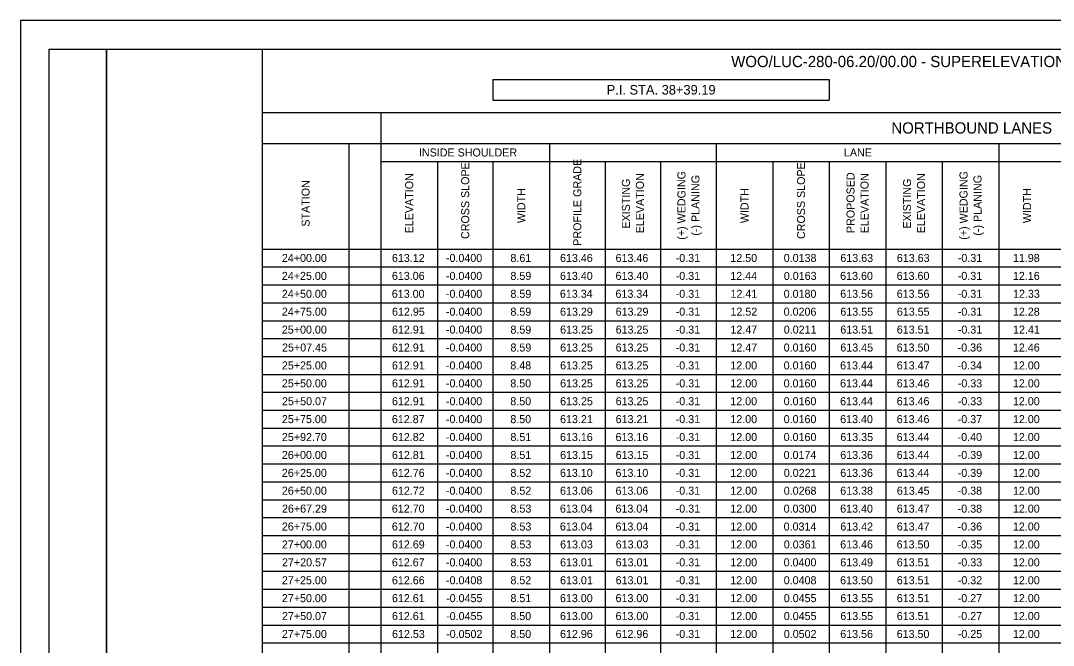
# Model space of a CAD drawing. Extents: x 0 to 34, y 0 to 22.
# Drawn here: x 0 to 18.06, y 11.08 to 22 of the extents above; entities that cross this region are included whole.
import ezdxf

# ---------------------------------------------------------------- set-up
doc = ezdxf.new("R2010")
doc.units = 0
for name, color, linetype in [('SH_Border', 7, 'Continuous'), ('SH_Cut_Line', 7, 'Continuous'), ('SH_Text', 7, 'Continuous')]:
    doc.layers.add(name, color=color, linetype=linetype)

msp = doc.modelspace()

# ---------------------------------------------------------------- linework, layer by layer
at = {"layer": 'SH_Border'}
for points in [[(0.5, 21.5), (1.5, 21.5), (1.5, 0.5), (0.5, 0.5)], [(1.5, 21.5), (33.5, 21.5), (33.5, 0.5), (1.5, 0.5)]]:
    msp.add_lwpolyline(points, close=True, dxfattribs=at)
at = {"layer": 'SH_Cut_Line'}
msp.add_lwpolyline([(0, 0), (34, 0), (34, 22), (0, 22)], close=True, dxfattribs=at)
at = {"layer": 'SH_Text'}
for p, q in [((4.225, 21.5), (5.74, 21.5)), ((4.225, 21.5), (4.225, 0.484)), ((8.26, 20.973), (14.14, 20.973)), ((8.26, 20.973), (8.26, 20.611)), ((14.14, 20.973), (14.14, 20.611)), ((8.26, 20.611), (14.14, 20.611)), ((4.225, 20.396), (29.277, 20.396)), ((6.3, 20.396), (6.3, 0.484)), ((4.225, 19.853), (29.277, 19.853)), ((5.74, 19.853), (5.74, 0.484)), ((9.249, 19.853), (9.249, 0.484)), ((12.164, 19.853), (12.164, 0.484)), ((17.105, 19.853), (17.105, 0.484)), ((6.3, 19.54), (26.938, 19.54)), ((7.289, 19.54), (7.289, 0.484)), ((8.26, 19.54), (8.26, 0.484)), ((10.22, 19.54), (10.22, 0.484)), ((11.192, 19.54), (11.192, 0.484)), ((13.152, 19.54), (13.152, 0.484)), ((14.14, 19.54), (14.14, 0.484)), ((15.129, 19.54), (15.129, 0.484)), ((16.117, 19.54), (16.117, 0.484)), ((4.225, 18.008), (29.277, 18.008)), ((4.225, 17.695), (29.277, 17.695)), ((4.225, 17.382), (29.277, 17.382)), ((4.225, 17.069), (29.277, 17.069)), ((4.225, 16.756), (29.277, 16.756)), ((4.225, 16.444), (29.277, 16.444)), ((4.225, 16.131), (29.277, 16.131)), ((4.225, 15.818), (29.277, 15.818)), ((4.225, 15.505), (29.277, 15.505)), ((4.225, 15.192), (29.277, 15.192)), ((4.225, 14.879), (29.277, 14.879)), ((4.225, 14.566), (29.277, 14.566)), ((4.225, 14.253), (29.277, 14.253)), ((4.225, 13.94), (29.277, 13.94)), ((4.225, 13.627), (29.277, 13.627)), ((4.225, 13.314), (29.277, 13.314)), ((4.225, 13.001), (29.277, 13.001)), ((4.225, 12.688), (29.277, 12.688)), ((4.225, 12.375), (29.277, 12.375)), ((4.225, 12.062), (29.277, 12.062)), ((4.225, 11.749), (29.277, 11.749)), ((4.225, 11.436), (29.277, 11.436)), ((4.225, 11.124), (29.277, 11.124))]:
    msp.add_line(p, q, dxfattribs=at)

# ---------------------------------------------------------------- texts
for s, height, p in [('WOO/LUC-280-06.20/00.00 - SUPERELEVATION TABLE', 0.196, (12.425, 21.188)), ('P.I. STA. 38+39.19', 0.168, (10.248, 20.708)), ('NORTHBOUND LANES', 0.196, (15.226, 20.027)), ('INSIDE SHOULDER', 0.14, (6.965, 19.626)), ('LANE', 0.14, (14.397, 19.626)), ('24+00.00', 0.14, (4.568, 17.782)), ('613.12', 0.14, (6.493, 17.782)), ('-0.0400', 0.14, (7.437, 17.782)), ('8.61', 0.14, (8.565, 17.782)), ('613.46', 0.14, (9.432, 17.782)), ('613.46', 0.14, (10.403, 17.782)), ('-0.31', 0.14, (11.455, 17.782)), ('12.50', 0.14, (12.41, 17.782)), ('0.0138', 0.14, (13.344, 17.782)), ('613.63', 0.14, (14.334, 17.782)), ('613.63', 0.14, (15.322, 17.782)), ('-0.31', 0.14, (16.388, 17.782)), ('11.98', 0.14, (17.352, 17.782)), ('24+25.00', 0.14, (4.568, 17.469)), ('613.06', 0.14, (6.492, 17.469)), ('-0.0400', 0.14, (7.437, 17.469)), ('8.59', 0.14, (8.565, 17.469)), ('613.40', 0.14, (9.431, 17.469)), ('613.40', 0.14, (10.403, 17.469)), ('-0.31', 0.14, (11.455, 17.469)), ('12.44', 0.14, (12.41, 17.469)), ('0.0163', 0.14, (13.346, 17.469)), ('613.60', 0.14, (14.331, 17.469)), ('613.60', 0.14, (15.319, 17.469)), ('-0.31', 0.14, (16.388, 17.469)), ('12.16', 0.14, (17.352, 17.469)), ('24+50.00', 0.14, (4.568, 17.156)), ('613.00', 0.14, (6.491, 17.156)), ('-0.0400', 0.14, (7.437, 17.156)), ('8.59', 0.14, (8.565, 17.156)), ('613.34', 0.14, (9.43, 17.156)), ('613.34', 0.14, (10.402, 17.156)), ('-0.31', 0.14, (11.455, 17.156)), ('12.41', 0.14, (12.413, 17.156)), ('0.0180', 0.14, (13.343, 17.156)), ('613.56', 0.14, (14.332, 17.156)), ('613.56', 0.14, (15.32, 17.156)), ('-0.31', 0.14, (16.388, 17.156)), ('12.33', 0.14, (17.354, 17.156)), ('24+75.00', 0.14, (4.568, 16.843)), ('612.95', 0.14, (6.494, 16.843)), ('-0.0400', 0.14, (7.437, 16.843)), ('8.59', 0.14, (8.565, 16.843)), ('613.29', 0.14, (9.433, 16.843)), ('613.29', 0.14, (10.405, 16.843)), ('-0.31', 0.14, (11.455, 16.843)), ('12.52', 0.14, (12.413, 16.843)), ('0.0206', 0.14, (13.343, 16.843)), ('613.55', 0.14, (14.334, 16.843)), ('613.55', 0.14, (15.322, 16.843)), ('-0.31', 0.14, (16.388, 16.843)), ('12.28', 0.14, (17.352, 16.843)), ('25+00.00', 0.14, (4.568, 16.53)), ('612.91', 0.14, (6.493, 16.53)), ('-0.0400', 0.14, (7.437, 16.53)), ('8.59', 0.14, (8.565, 16.53)), ('613.25', 0.14, (9.434, 16.53)), ('613.25', 0.14, (10.405, 16.53)), ('-0.31', 0.14, (11.455, 16.53)), ('12.47', 0.14, (12.412, 16.53)), ('0.0211', 0.14, (13.345, 16.53)), ('613.51', 0.14, (14.333, 16.53)), ('613.51', 0.14, (15.321, 16.53)), ('-0.31', 0.14, (16.388, 16.53)), ('12.41', 0.14, (17.354, 16.53)), ('25+07.45', 0.14, (4.571, 16.217)), ('612.91', 0.14, (6.493, 16.217)), ('-0.0400', 0.14, (7.437, 16.217)), ('8.59', 0.14, (8.565, 16.217)), ('613.25', 0.14, (9.434, 16.217)), ('613.25', 0.14, (10.405, 16.217)), ('-0.31', 0.14, (11.455, 16.217)), ('12.47', 0.14, (12.412, 16.217)), ('0.0160', 0.14, (13.343, 16.217)), ('613.45', 0.14, (14.334, 16.217)), ('613.50', 0.14, (15.319, 16.217)), ('-0.36', 0.14, (16.386, 16.217)), ('12.46', 0.14, (17.352, 16.217)), ('25+25.00', 0.14, (4.568, 15.904)), ('612.91', 0.14, (6.493, 15.904)), ('-0.0400', 0.14, (7.437, 15.904)), ('8.48', 0.14, (8.563, 15.904)), ('613.25', 0.14, (9.434, 15.904)), ('613.25', 0.14, (10.405, 15.904)), ('-0.31', 0.14, (11.455, 15.904)), ('12.00', 0.14, (12.41, 15.904)), ('0.0160', 0.14, (13.343, 15.904)), ('613.44', 0.14, (14.33, 15.904)), ('613.47', 0.14, (15.321, 15.904)), ('-0.34', 0.14, (16.385, 15.904)), ('12.00', 0.14, (17.352, 15.904)), ('25+50.00', 0.14, (4.568, 15.591)), ('612.91', 0.14, (6.493, 15.591)), ('-0.0400', 0.14, (7.437, 15.591)), ('8.50', 0.14, (8.563, 15.591)), ('613.25', 0.14, (9.434, 15.591)), ('613.25', 0.14, (10.405, 15.591)), ('-0.31', 0.14, (11.455, 15.591)), ('12.00', 0.14, (12.41, 15.591)), ('0.0160', 0.14, (13.343, 15.591)), ('613.44', 0.14, (14.33, 15.591)), ('613.46', 0.14, (15.32, 15.591)), ('-0.33', 0.14, (16.388, 15.591)), ('12.00', 0.14, (17.352, 15.591)), ('25+50.07', 0.14, (4.57, 15.278)), ('612.91', 0.14, (6.493, 15.278)), ('-0.0400', 0.14, (7.437, 15.278)), ('8.50', 0.14, (8.563, 15.278)), ('613.25', 0.14, (9.434, 15.278)), ('613.25', 0.14, (10.405, 15.278)), ('-0.31', 0.14, (11.455, 15.278)), ('12.00', 0.14, (12.41, 15.278)), ('0.0160', 0.14, (13.343, 15.278)), ('613.44', 0.14, (14.33, 15.278)), ('613.46', 0.14, (15.32, 15.278)), ('-0.33', 0.14, (16.388, 15.278)), ('12.00', 0.14, (17.352, 15.278)), ('25+75.00', 0.14, (4.568, 14.965)), ('612.87', 0.14, (6.492, 14.965)), ('-0.0400', 0.14, (7.437, 14.965)), ('8.50', 0.14, (8.563, 14.965)), ('613.21', 0.14, (9.433, 14.965)), ('613.21', 0.14, (10.405, 14.965)), ('-0.31', 0.14, (11.455, 14.965)), ('12.00', 0.14, (12.41, 14.965)), ('0.0160', 0.14, (13.343, 14.965)), ('613.40', 0.14, (14.331, 14.965)), ('613.46', 0.14, (15.32, 14.965)), ('-0.37', 0.14, (16.387, 14.965)), ('12.00', 0.14, (17.352, 14.965)), ('25+92.70', 0.14, (4.568, 14.652)), ('612.82', 0.14, (6.493, 14.652)), ('-0.0400', 0.14, (7.437, 14.652)), ('8.51', 0.14, (8.565, 14.652)), ('613.16', 0.14, (9.432, 14.652)), ('613.16', 0.14, (10.403, 14.652)), ('-0.31', 0.14, (11.455, 14.652)), ('12.00', 0.14, (12.41, 14.652)), ('0.0160', 0.14, (13.343, 14.652)), ('613.35', 0.14, (14.334, 14.652)), ('613.44', 0.14, (15.319, 14.652)), ('-0.40', 0.14, (16.385, 14.652)), ('12.00', 0.14, (17.352, 14.652)), ('26+00.00', 0.14, (4.568, 14.339)), ('612.81', 0.14, (6.493, 14.339)), ('-0.0400', 0.14, (7.437, 14.339)), ('8.51', 0.14, (8.565, 14.339)), ('613.15', 0.14, (9.434, 14.339)), ('613.15', 0.14, (10.405, 14.339)), ('-0.31', 0.14, (11.455, 14.339)), ('12.00', 0.14, (12.41, 14.339)), ('0.0174', 0.14, (13.342, 14.339)), ('613.36', 0.14, (14.332, 14.339)), ('613.44', 0.14, (15.319, 14.339)), ('-0.39', 0.14, (16.387, 14.339)), ('12.00', 0.14, (17.352, 14.339)), ('26+25.00', 0.14, (4.568, 14.026)), ('612.76', 0.14, (6.492, 14.026)), ('-0.0400', 0.14, (7.437, 14.026)), ('8.52', 0.14, (8.565, 14.026)), ('613.10', 0.14, (9.431, 14.026)), ('613.10', 0.14, (10.403, 14.026)), ('-0.31', 0.14, (11.455, 14.026)), ('12.00', 0.14, (12.41, 14.026)), ('0.0221', 0.14, (13.345, 14.026)), ('613.36', 0.14, (14.332, 14.026)), ('613.44', 0.14, (15.319, 14.026)), ('-0.39', 0.14, (16.387, 14.026)), ('12.00', 0.14, (17.352, 14.026)), ('26+50.00', 0.14, (4.568, 13.714)), ('612.72', 0.14, (6.493, 13.714)), ('-0.0400', 0.14, (7.437, 13.714)), ('8.52', 0.14, (8.565, 13.714)), ('613.06', 0.14, (9.432, 13.714)), ('613.06', 0.14, (10.403, 13.714)), ('-0.31', 0.14, (11.455, 13.714)), ('12.00', 0.14, (12.41, 13.714)), ('0.0268', 0.14, (13.344, 13.714)), ('613.38', 0.14, (14.332, 13.714)), ('613.45', 0.14, (15.322, 13.714)), ('-0.38', 0.14, (16.386, 13.714)), ('12.00', 0.14, (17.352, 13.714)), ('26+67.29', 0.14, (4.57, 13.401)), ('612.70', 0.14, (6.491, 13.401)), ('-0.0400', 0.14, (7.437, 13.401)), ('8.53', 0.14, (8.566, 13.401)), ('613.04', 0.14, (9.43, 13.401)), ('613.04', 0.14, (10.402, 13.401)), ('-0.31', 0.14, (11.455, 13.401)), ('12.00', 0.14, (12.41, 13.401)), ('0.0300', 0.14, (13.343, 13.401)), ('613.40', 0.14, (14.331, 13.401)), ('613.47', 0.14, (15.321, 13.401)), ('-0.38', 0.14, (16.386, 13.401)), ('12.00', 0.14, (17.352, 13.401)), ('26+75.00', 0.14, (4.568, 13.088)), ('612.70', 0.14, (6.491, 13.088)), ('-0.0400', 0.14, (7.437, 13.088)), ('8.53', 0.14, (8.566, 13.088)), ('613.04', 0.14, (9.43, 13.088)), ('613.04', 0.14, (10.402, 13.088)), ('-0.31', 0.14, (11.455, 13.088)), ('12.00', 0.14, (12.41, 13.088)), ('0.0314', 0.14, (13.342, 13.088)), ('613.42', 0.14, (14.333, 13.088)), ('613.47', 0.14, (15.321, 13.088)), ('-0.36', 0.14, (16.386, 13.088)), ('12.00', 0.14, (17.352, 13.088)), ('27+00.00', 0.14, (4.568, 12.775)), ('612.69', 0.14, (6.493, 12.775)), ('-0.0400', 0.14, (7.437, 12.775)), ('8.53', 0.14, (8.566, 12.775)), ('613.03', 0.14, (9.434, 12.775)), ('613.03', 0.14, (10.406, 12.775)), ('-0.31', 0.14, (11.455, 12.775)), ('12.00', 0.14, (12.41, 12.775)), ('0.0361', 0.14, (13.345, 12.775)), ('613.46', 0.14, (14.332, 12.775)), ('613.50', 0.14, (15.319, 12.775)), ('-0.35', 0.14, (16.388, 12.775)), ('12.00', 0.14, (17.352, 12.775)), ('27+20.57', 0.14, (4.57, 12.462)), ('612.67', 0.14, (6.492, 12.462)), ('-0.0400', 0.14, (7.437, 12.462)), ('8.53', 0.14, (8.566, 12.462)), ('613.01', 0.14, (9.433, 12.462)), ('613.01', 0.14, (10.405, 12.462)), ('-0.31', 0.14, (11.455, 12.462)), ('12.00', 0.14, (12.41, 12.462)), ('0.0400', 0.14, (13.343, 12.462)), ('613.49', 0.14, (14.333, 12.462)), ('613.51', 0.14, (15.321, 12.462)), ('-0.33', 0.14, (16.388, 12.462)), ('12.00', 0.14, (17.352, 12.462)), ('27+25.00', 0.14, (4.568, 12.149)), ('612.66', 0.14, (6.492, 12.149)), ('-0.0408', 0.14, (7.438, 12.149)), ('8.52', 0.14, (8.565, 12.149)), ('613.01', 0.14, (9.433, 12.149)), ('613.01', 0.14, (10.405, 12.149)), ('-0.31', 0.14, (11.455, 12.149)), ('12.00', 0.14, (12.41, 12.149)), ('0.0408', 0.14, (13.344, 12.149)), ('613.50', 0.14, (14.331, 12.149)), ('613.51', 0.14, (15.321, 12.149)), ('-0.32', 0.14, (16.388, 12.149)), ('12.00', 0.14, (17.352, 12.149)), ('27+50.00', 0.14, (4.568, 11.836)), ('612.61', 0.14, (6.493, 11.836)), ('-0.0455', 0.14, (7.44, 11.836)), ('8.51', 0.14, (8.565, 11.836)), ('613.00', 0.14, (9.431, 11.836)), ('613.00', 0.14, (10.403, 11.836)), ('-0.31', 0.14, (11.455, 11.836)), ('12.00', 0.14, (12.41, 11.836)), ('0.0455', 0.14, (13.345, 11.836)), ('613.55', 0.14, (14.334, 11.836)), ('613.51', 0.14, (15.321, 11.836)), ('-0.27', 0.14, (16.387, 11.836)), ('12.00', 0.14, (17.352, 11.836)), ('27+50.07', 0.14, (4.57, 11.523)), ('612.61', 0.14, (6.493, 11.523)), ('-0.0455', 0.14, (7.44, 11.523)), ('8.50', 0.14, (8.563, 11.523)), ('613.00', 0.14, (9.431, 11.523)), ('613.00', 0.14, (10.403, 11.523)), ('-0.31', 0.14, (11.455, 11.523)), ('12.00', 0.14, (12.41, 11.523)), ('0.0455', 0.14, (13.345, 11.523)), ('613.55', 0.14, (14.334, 11.523)), ('613.51', 0.14, (15.321, 11.523)), ('-0.27', 0.14, (16.387, 11.523)), ('12.00', 0.14, (17.352, 11.523)), ('27+75.00', 0.14, (4.568, 11.21)), ('612.53', 0.14, (6.494, 11.21)), ('-0.0502', 0.14, (7.44, 11.21)), ('8.50', 0.14, (8.563, 11.21)), ('612.96', 0.14, (9.432, 11.21)), ('612.96', 0.14, (10.403, 11.21)), ('-0.31', 0.14, (11.455, 11.21)), ('12.00', 0.14, (12.41, 11.21)), ('0.0502', 0.14, (13.345, 11.21)), ('613.56', 0.14, (14.332, 11.21)), ('613.50', 0.14, (15.319, 11.21)), ('-0.25', 0.14, (16.388, 11.21)), ('12.00', 0.14, (17.352, 11.21))]:
    msp.add_text(s, height=height, dxfattribs=at).set_placement(p)
for s, p in [('CROSS SLOPE', (7.844, 18.183)), ('PROFILE GRADE', (9.804, 18.066)), ('CROSS SLOPE', (13.716, 18.183)), ('(+) WEDGING', (11.625, 18.17)), ('PROPOSED ', (14.582, 18.287)), ('(+) WEDGING', (16.558, 18.17)), ('STATION', (5.053, 18.4)), ('ELEVATION', (6.864, 18.283)), ('EXISTING ', (10.654, 18.365)), ('ELEVATION', (10.899, 18.283)), ('(-) PLANING', (11.87, 18.242)), ('ELEVATION', (14.827, 18.283)), ('EXISTING ', (15.57, 18.365)), ('ELEVATION', (15.815, 18.283)), ('(-) PLANING', (16.803, 18.242)), ('WIDTH', (8.824, 18.461)), ('WIDTH', (12.728, 18.461)), ('WIDTH', (17.669, 18.461))]:
    msp.add_text(s, height=0.14, rotation=90, dxfattribs=at).set_placement(p)

doc.saveas('drawing.dxf')
